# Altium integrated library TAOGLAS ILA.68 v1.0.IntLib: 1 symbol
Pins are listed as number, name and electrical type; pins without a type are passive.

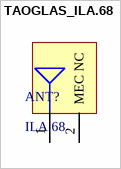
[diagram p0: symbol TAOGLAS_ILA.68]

## TAOGLAS_ILA.68
designator ANT?, comment ILA.68
LTCC UWB Antenna Covering 6-8.5GHz; ComponentLibStatus: Created; MFG: Taoglas; Temp_High: +85C; Temp_Low: -40C
footprint TAOGLAS_ILA.68 (LTCC UWB Antenna Covering 6-8.5GHz)
pins: 1 RF OUT, 2 MEC NC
